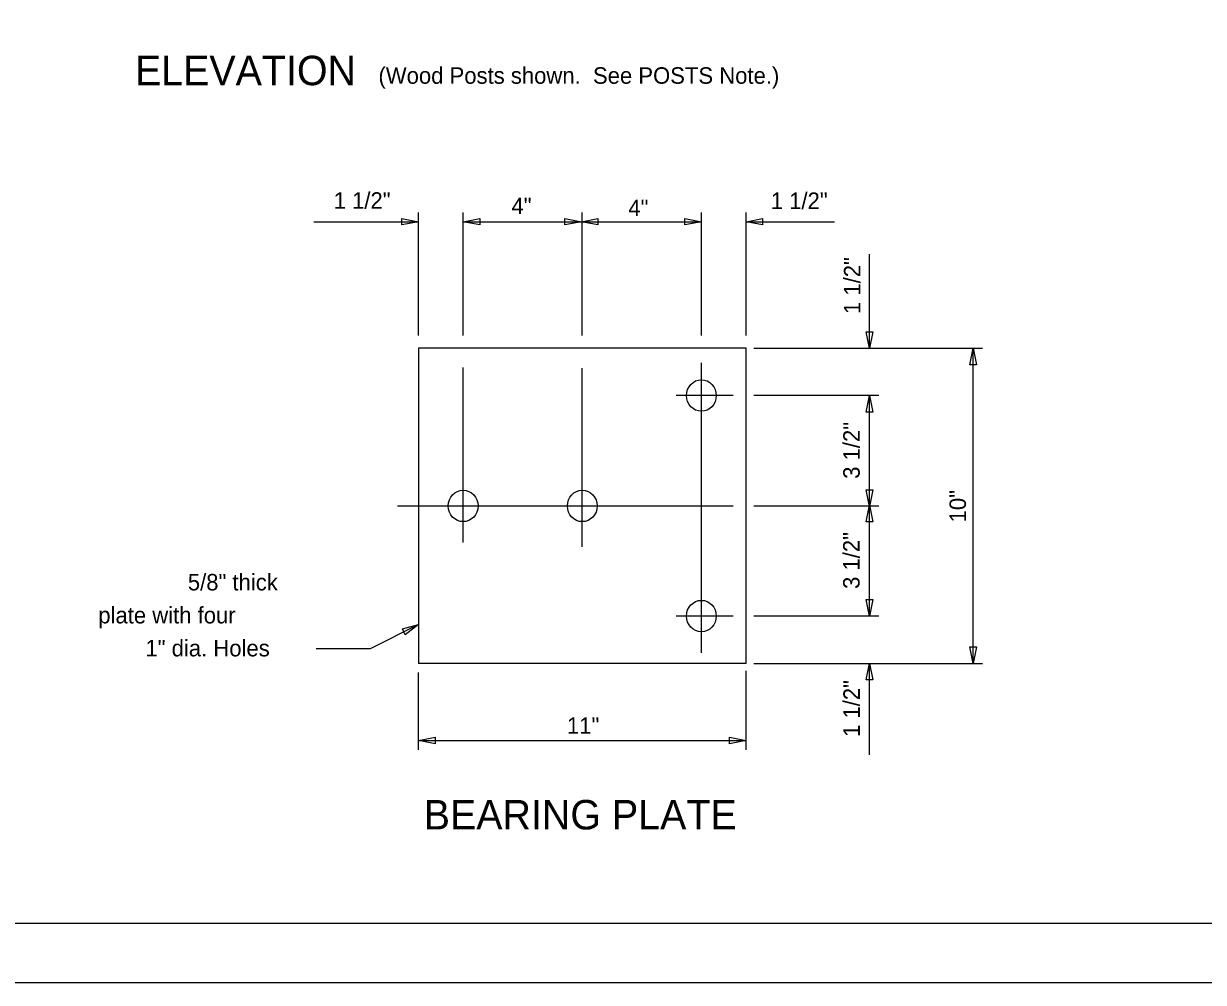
# Model space of a CAD drawing. Extents: x 0 to 34, y 0 to 22.
# Drawn here: x 11.68 to 21.69, y 0 to 8.14 of the extents above; entities that cross this region are included whole.
import ezdxf

# ---------------------------------------------------------------- set-up
doc = ezdxf.new("R2010")
doc.units = 0
for name, color, linetype in [('SH_Border', 7, 'Continuous'), ('SH_Cut_Line', 7, 'Continuous'), ('ST_Details', 7, 'Continuous'), ('ST_Text', 7, 'Continuous')]:
    doc.layers.add(name, color=color, linetype=linetype)

msp = doc.modelspace()

# ---------------------------------------------------------------- linework, layer by layer
at = {"layer": 'SH_Border'}
msp.add_lwpolyline([(2, 21.5), (33.5, 21.5), (33.5, 0.5), (2, 0.5)], close=True, dxfattribs=at)
at = {"layer": 'SH_Cut_Line'}
msp.add_lwpolyline([(0, 0), (34, 0), (34, 22), (0, 22)], close=True, dxfattribs=at)
at = {"layer": 'ST_Details'}
for p, q in [((15.03, 5.384), (15.03, 2.708)), ((17.81, 5.384), (15.03, 5.384)), ((17.81, 4.046), (17.81, 5.384)), ((15.409, 3.736), (15.409, 5.22)), ((16.42, 3.698), (16.42, 5.214)), ((17.431, 2.797), (17.431, 5.26)), ((17.702, 4.982), (17.218, 4.982)), ((14.851, 4.046), (17.146, 4.046)), ((17.146, 4.046), (17.702, 4.046)), ((17.81, 2.708), (17.81, 4.046)), ((17.702, 3.11), (17.218, 3.11)), ((17.81, 2.708), (15.03, 2.708))]:
    msp.add_line(p, q, dxfattribs=at)
for centre in [(17.431, 4.983), (15.409, 4.046), (16.42, 4.046), (17.431, 3.11)]:
    msp.add_ellipse(centre, major_axis=(0, 0.134), ratio=0.944544, dxfattribs=at)
at = {"layer": 'ST_Text'}
for p, q in [((15.03, 5.492), (15.03, 6.538)), ((15.409, 5.492), (15.409, 6.538)), ((16.42, 5.492), (16.42, 6.538)), ((17.431, 5.492), (17.431, 6.538)), ((17.81, 5.492), (17.81, 6.538)), ((14.14, 6.459), (15.029, 6.459)), ((15.409, 6.459), (16.413, 6.459)), ((16.413, 6.459), (17.431, 6.459)), ((17.81, 6.459), (18.561, 6.459)), ((18.858, 5.384), (18.858, 6.184)), ((17.877, 5.384), (19.816, 5.384)), ((19.738, 2.708), (19.738, 5.384)), ((18.936, 4.982), (17.877, 4.982)), ((18.858, 4.041), (18.858, 4.982)), ((17.877, 4.046), (18.936, 4.046)), ((18.858, 3.11), (18.858, 4.051)), ((18.936, 3.11), (17.877, 3.11)), ((17.877, 2.708), (19.816, 2.708)), ((18.858, 1.931), (18.858, 2.708)), ((15.03, 1.976), (15.03, 2.632)), ((17.81, 1.976), (17.81, 2.646)), ((15.03, 2.055), (17.81, 2.055))]:
    msp.add_line(p, q, dxfattribs=at)
for points in [[(14.889, 6.431), (14.889, 6.487), (15.029, 6.459)], [(15.549, 6.487), (15.549, 6.431), (15.409, 6.459)], [(16.273, 6.431), (16.273, 6.487), (16.413, 6.459)], [(16.553, 6.487), (16.553, 6.431), (16.413, 6.459)], [(17.291, 6.431), (17.291, 6.487), (17.431, 6.459)], [(17.95, 6.487), (17.95, 6.431), (17.81, 6.459)], [(18.83, 5.524), (18.886, 5.524), (18.858, 5.384)], [(19.766, 5.244), (19.71, 5.244), (19.738, 5.384)], [(18.886, 4.842), (18.83, 4.842), (18.858, 4.982)], [(18.83, 4.181), (18.886, 4.181), (18.858, 4.041)], [(18.886, 3.911), (18.83, 3.911), (18.858, 4.051)], [(18.83, 3.25), (18.886, 3.25), (18.858, 3.11)], [(14.918, 2.951), (14.893, 3.001), (15.03, 3.039)], [(19.71, 2.848), (19.766, 2.848), (19.738, 2.708)], [(18.886, 2.568), (18.83, 2.568), (18.858, 2.708)], [(15.17, 2.083), (15.17, 2.027), (15.03, 2.055)], [(17.67, 2.027), (17.67, 2.083), (17.81, 2.055)]]:
    msp.add_lwpolyline(points, close=True, dxfattribs=at)
msp.add_lwpolyline([(15.03, 3.039), (14.62, 2.832), (14.161, 2.832)], dxfattribs=at)

# ---------------------------------------------------------------- texts
for s, height, p in [('ELEVATION ', 0.25, (12.623, 7.618)), (' (Wood Posts shown.  See POSTS Note.) ', 0.14, (14.638, 7.63)), ('1 1/2"', 0.14, (14.31, 6.569)), ('1 1/2"', 0.14, (18.02, 6.567)), ('4"', 0.14, (15.819, 6.523)), ('4"', 0.14, (16.811, 6.507)), ('5/8" thick', 0.14, (13.072, 3.328)), ('plate with four', 0.14, (12.312, 3.048)), ('1" dia. Holes', 0.14, (12.712, 2.768)), ('11"', 0.14, (16.29, 2.111)), ('BEARING PLATE', 0.25, (15.074, 1.299))]:
    msp.add_text(s, height=height, dxfattribs=at).set_placement(p)
for s, p in [('1 1/2"', (18.781, 5.675)), ('3 1/2"', (18.775, 4.276)), ('10"', (19.677, 3.906)), ('3 1/2"', (18.774, 3.341)), ('1 1/2" ', (18.776, 2.084))]:
    msp.add_text(s, height=0.14, rotation=90, dxfattribs=at).set_placement(p)

doc.saveas('drawing.dxf')
